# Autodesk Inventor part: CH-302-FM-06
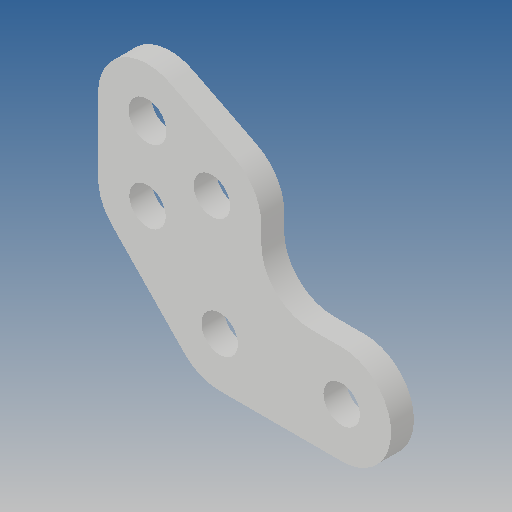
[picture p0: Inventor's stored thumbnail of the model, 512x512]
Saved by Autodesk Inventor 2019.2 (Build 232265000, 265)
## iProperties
Created: 2013-03
Part Number: CH-302-FM-06
Material: Ogólny
Document SubType Name: Modeling
Designer: CADENGINEERING4
Density: 1 g/cm^3
Appearance: Domyślna
Author: CADENGINEERING4
Revision Number: ÈÎºÎ
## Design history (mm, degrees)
feature "À­Éì1"
node "Bryła1"
